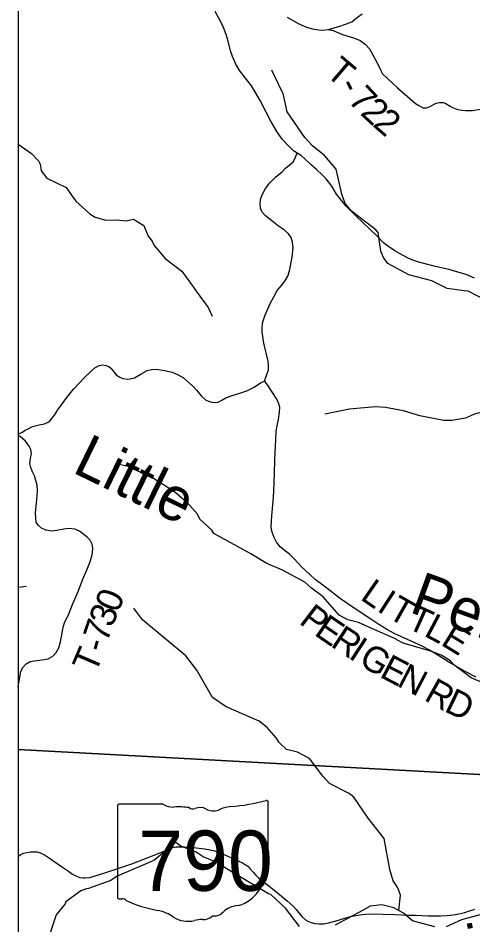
# Model space of a CAD drawing. Extents: x -1.8 to 75.7, y -2 to 25.
# Drawn here: x 43.8 to 44.794, y 18.595 to 20.577 of the extents above; entities that cross this region are included whole.
import ezdxf

# ---------------------------------------------------------------- set-up
doc = ezdxf.new("R2010")
doc.units = 0
for name, color, linetype in [('GM_X_County_Road', 7, 'Continuous'), ('GM_X_Minor_River', 7, 'Continuous'), ('GM_X_Minor_River_Text', 7, 'Continuous'), ('GM_X_State_Location', 7, 'Continuous'), ('GM_X_State_Route', 7, 'Continuous'), ('GM_X_State_Shield', 7, 'Continuous'), ('GM_X_Township', 7, 'Continuous'), ('GM_X_Township_Road', 7, 'Continuous'), ('GM_X_Township_Road_Text', 7, 'Continuous'), ('SH_Data', 7, 'Continuous')]:
    doc.layers.add(name, color=color, linetype=linetype)

msp = doc.modelspace()

# ---------------------------------------------------------------- linework, layer by layer
at = {"layer": 'GM_X_County_Road'}
for points in [[(44.7979, 20.009), (44.7792, 20.0165), (44.7663, 20.0203), (44.7442, 20.0269), (44.7092, 20.0352), (44.6757, 20.044), (44.6631, 20.0483), (44.6529, 20.0528), (44.6428, 20.0578), (44.6337, 20.063), (44.6238, 20.0689), (44.6077, 20.0795), (44.5987, 20.0863), (44.5833, 20.1023), (44.5689, 20.1159), (44.5548, 20.1291), (44.5376, 20.1456), (44.517, 20.1665), (44.5045, 20.1814), (44.4961, 20.1923), (44.4855, 20.2102), (44.4737, 20.2259), (44.4647, 20.235), (44.452, 20.2466), (44.4408, 20.2567), (44.427, 20.27), (44.4184, 20.2771), (44.41, 20.2821), (44.402, 20.2875), (44.3889, 20.3002), (44.3773, 20.3126), (44.3655, 20.3294), (44.3528, 20.3518), (44.342, 20.372), (44.3293, 20.397), (44.3192, 20.4149), (44.3102, 20.4291), (44.2972, 20.4463), (44.285, 20.462), (44.2759, 20.4768), (44.2686, 20.4936), (44.2643, 20.5059), (44.2589, 20.5268), (44.2548, 20.5416), (44.2492, 20.5571), (44.2424, 20.5709), (44.2307, 20.5918)], [(44.3885, 20.5797), (44.4121, 20.5656), (44.4304, 20.5572), (44.4433, 20.5538), (44.4571, 20.5516), (44.4655, 20.5513), (44.4777, 20.5521), (44.5012, 20.5588), (44.5178, 20.5647), (44.5293, 20.5695), (44.5389, 20.577), (44.5518, 20.5867)]]:
    msp.add_lwpolyline(points, dxfattribs=at)
at = {"layer": 'GM_X_Minor_River'}
for points in [[(44.8204, 19.9613), (44.7836, 19.9803), (44.7749, 19.981), (44.7376, 19.9863), (44.7045, 20.0026), (44.6539, 20.0163), (44.6085, 20.0409), (44.5987, 20.0542), (44.5931, 20.068), (44.5868, 20.1089), (44.5816, 20.1147), (44.5284, 20.1555), (44.5146, 20.1723), (44.5076, 20.1923), (44.4949, 20.247), (44.4694, 20.277), (44.4436, 20.2984), (44.4271, 20.316), (44.3883, 20.3723), (44.3797, 20.4128), (44.375, 20.4202), (44.3548, 20.4634)], [(43.8002, 20.302), (43.8297, 20.281), (43.8447, 20.2653), (43.8486, 20.2583), (43.8504, 20.2431), (43.8632, 20.2271), (43.9053, 20.2068), (43.9219, 20.1827), (43.9263, 20.1772), (43.9565, 20.1497), (43.9687, 20.1425), (43.9919, 20.1353), (44.0162, 20.136), (44.0361, 20.1338), (44.0525, 20.1375), (44.0752, 20.1242), (44.0846, 20.1008), (44.093, 20.0895), (44.0972, 20.0799), (44.1214, 20.0521), (44.1576, 20.0244), (44.1866, 19.9851), (44.1891, 19.9801), (44.2152, 19.9443), (44.2244, 19.9254)], [(44.824, 19.7182), (44.8004, 19.7125), (44.7978, 19.7117), (44.7777, 19.7026), (44.7483, 19.6979), (44.7309, 19.6975), (44.6783, 19.7076), (44.6424, 19.719), (44.6031, 19.7257), (44.5815, 19.7272), (44.5245, 19.7225), (44.4708, 19.7117)], [(44.8192, 19.1226), (44.7904, 19.1347), (44.7522, 19.1635), (44.7454, 19.1722), (44.7246, 19.1847), (44.7042, 19.1926), (44.6418, 19.2111), (44.6282, 19.2179), (44.6266, 19.2198), (44.5729, 19.2425), (44.5438, 19.2557), (44.5211, 19.2617), (44.5018, 19.2723), (44.4667, 19.3122), (44.4413, 19.3307), (44.4269, 19.3444), (44.3778, 19.3705), (44.3437, 19.3852), (44.3089, 19.4064), (44.2276, 19.4503), (44.2234, 19.4579), (44.197, 19.4822), (44.192, 19.4928), (44.1693, 19.5186), (44.164, 19.5228), (44.1421, 19.5417), (44.0963, 19.5705), (44.0403, 19.5974), (44.0211, 19.6015), (44.0211, 19.6011)], [(43.8002, 19.3335), (43.8078, 19.3338), (43.818, 19.3353), (43.8172, 19.3349)], [(44.6322, 18.6266), (44.6356, 18.6598), (44.6301, 18.6759), (44.6196, 18.6915), (44.6128, 18.716), (44.6005, 18.7836), (44.5655, 18.828), (44.534, 18.8738), (44.5237, 18.8821), (44.4805, 18.904), (44.4659, 18.92), (44.4372, 18.9589), (44.4111, 18.9723), (44.3864, 18.9784), (44.3702, 18.9941), (44.3652, 19.003), (44.3443, 19.0261), (44.3266, 19.0399), (44.255, 19.0714), (44.2246, 19.0918), (44.1905, 19.1517), (44.1669, 19.1829), (44.0718, 19.2615), (44.0565, 19.2821), (44.0533, 19.2871)], [(44.4148, 18.5913), (44.3845, 18.6312), (44.3528, 18.6615), (44.3471, 18.6626), (44.2661, 18.7118), (44.2313, 18.733), (44.2045, 18.7436), (44.189, 18.7535), (44.1557, 18.7671), (44.1425, 18.7761), (44.1383, 18.778), (44.1289, 18.7617), (44.1123, 18.7479), (44.0964, 18.7354), (44.0556, 18.7178), (44.0163, 18.7013), (44.0027, 18.6922), (43.9536, 18.6742), (43.9498, 18.6738), (43.9369, 18.6692), (43.9045, 18.6456), (43.9026, 18.641), (43.8833, 18.617), (43.8701, 18.5778)], [(45.1478, 18.7045), (45.1443, 18.703), (45.1182, 18.6976), (45.0933, 18.688), (45.0883, 18.6903), (45.0774, 18.6876), (45.0619, 18.6891), (45.0581, 18.6891), (45.0498, 18.691), (45.04, 18.689), (45.004, 18.6947), (44.9791, 18.6935), (44.9459, 18.6759), (44.9425, 18.6698), (44.8877, 18.6438), (44.8642, 18.6316), (44.8204, 18.6197), (44.7694, 18.6059), (44.7358, 18.5906)], [(44.7112, 18.5905), (44.6862, 18.5969), (44.662, 18.6037), (44.6427, 18.6208), (44.6212, 18.6325), (44.5951, 18.6385), (44.5694, 18.6358), (44.5528, 18.6262), (44.4927, 18.5942)]]:
    msp.add_lwpolyline(points, dxfattribs=at)
at = {"layer": 'GM_X_State_Route'}
for points in [[(43.8002, 18.7454), (43.8058, 18.7486), (43.8123, 18.7516), (43.8194, 18.7534), (43.8275, 18.7547), (43.8352, 18.7547), (43.8421, 18.7543), (43.8486, 18.7524), (43.8575, 18.7482), (43.8688, 18.7405), (43.8946, 18.7226), (43.91, 18.7121), (43.9193, 18.7056), (43.9278, 18.7012), (43.9349, 18.6987), (43.9422, 18.6979), (43.9469, 18.6977), (43.9566, 18.6987), (43.9683, 18.7018), (43.9898, 18.7087), (44.0488, 18.7287), (44.0788, 18.7399), (44.0978, 18.7476), (44.1278, 18.7599), (44.1357, 18.7632), (44.145, 18.7652), (44.1538, 18.7656), (44.1637, 18.7656), (44.1829, 18.7638), (44.2083, 18.7609), (44.2202, 18.7589), (44.2295, 18.7565), (44.252, 18.748), (44.2743, 18.7381), (44.2903, 18.7304), (44.2962, 18.7271), (44.3019, 18.7231), (44.3075, 18.7176), (44.314, 18.7099), (44.3193, 18.7042), (44.3256, 18.6979), (44.3313, 18.6927), (44.3367, 18.6886), (44.3442, 18.6829), (44.3671, 18.6649), (44.3888, 18.6467), (44.4014, 18.6357), (44.4077, 18.6288), (44.4131, 18.6223), (44.4208, 18.6124), (44.4285, 18.6057), (44.4336, 18.6027), (44.4405, 18.6003), (44.4484, 18.5982), (44.4573, 18.5974), (44.4678, 18.5974), (44.4786, 18.5992), (44.4924, 18.6031), (44.4927, 18.6032)], [(44.4927, 18.6032), (44.5163, 18.6104), (44.5304, 18.6138), (44.5465, 18.6167), (44.56, 18.6185), (44.5698, 18.6191), (44.6243, 18.6175), (44.6543, 18.6163), (44.6688, 18.6159), (44.6972, 18.6149), (44.724, 18.6148), (44.7381, 18.6157), (44.7507, 18.6171), (44.7631, 18.6191), (44.7762, 18.6223), (44.7845, 18.6248), (44.7945, 18.628), (44.798, 18.6293)]]:
    msp.add_lwpolyline(points, dxfattribs=at)
at = {"layer": 'GM_X_State_Shield'}
for p, q in [((44.017, 18.8553), (44.017, 18.6552)), ((44.1168, 18.8588), (44.0203, 18.8588)), ((44.3466, 18.7591), (44.3466, 18.8637)), ((44.3466, 18.7591), (44.3466, 18.7591))]:
    msp.add_line(p, q, dxfattribs=at)
for centre, major_axis, start_param, end_param in [((44.0208, 18.8558), (0.00382, 0), 1.712693, 3.28349), ((44.1398, 18.882), (0.037, 0), 4.042523, 4.731795), ((44.152, 18.7464), (0.133, 0), 1.404758, 1.657858), ((44.2738, 18.7977), (0.0703, 0), 1.699011, 2.107814), ((44.2292, 19.1316), (0.3495, 0), 4.814394, 5.042369), ((44.3429, 18.8642), (0.00367, 0), 6.141152, 7.989035), ((44.1822, 18.8568), (0.0107, 0), 3.836095, 5.185415), ((44.1979, 18.8337), (0.0222, 0), 0.950623, 2.079405), ((44.2266, 18.8654), (0.0267, 0), 4.081561, 5.145723), ((44.3457, 18.7514), (0.00568, 0), 1.883978, 3.671073), ((44.3427, 18.7587), (0.00393, 0), 5.05454, 6.418171), ((44.3096, 18.7381), (0.0341, 0), 5.934695, 6.695948), ((44.3597, 18.7152), (0.0248, 0), 2.387724, 3.262537), ((44.2488, 18.7019), (0.0874, 0), 5.101752, 6.440018), ((44.0208, 18.6548), (0.00385, 0), 3.00124, 4.508301), ((44.0214, 18.6753), (0.0294, 0), 4.665946, 4.897461), ((44.0274, 18.6437), (0.0106, 0), 0.519207, 1.627899), ((44.1612, 18.8235), (0.2524, 0), 4.195997, 4.488961), ((44.2856, 18.599), (0.0479, 0), 1.647645, 2.488434), ((44.086, 18.5653), (0.079, 0), 0.823519, 1.323587), ((44.2282, 18.6083), (0.00752, 0), 1.147584, 2.315152), ((44.225, 18.6358), (0.0282, 0), 4.937069, 5.64225), ((44.1714, 18.6427), (0.0501, 0), 4.026481, 4.996735), ((44.2004, 18.5735), (0.0412, 0), 1.495662, 1.94098), ((44.204, 18.6277), (0.0267, 0), 4.691044, 5.507374)]:
    msp.add_ellipse(centre, major_axis=major_axis, ratio=0.8, start_param=start_param, end_param=end_param, dxfattribs=at)
at = {"layer": 'GM_X_Township'}
for points in [[(48.1876, 22.5121), (43.8002, 22.5121), (43.8002, 18.978)], [(43.8002, 18.978), (44.8356, 18.9224), (45.3865, 18.8952), (46.1197, 18.859), (46.3714, 18.8466), (46.9192, 18.8195), (47.1815, 18.806), (47.9522, 18.7663), (48.0201, 19.5982), (48.0214, 19.6198), (48.0228, 19.6698), (48.0235, 19.6926), (48.0261, 19.7186), (48.0301, 19.7636), (48.0891, 20.7799), (48.1186, 21.2763), (48.1494, 21.7937), (48.1876, 22.5121)], [(43.8002, 18.978), (43.8002, 15.7121), (47.7632, 15.7121)], [(47.7632, 15.7121), (47.7893, 16.1371), (47.8138, 16.5363), (47.826, 16.7363), (47.8708, 17.4759), (47.8899, 17.791), (47.9266, 18.366), (47.9522, 18.7663), (47.1815, 18.806), (46.9192, 18.8195), (46.3714, 18.8466), (46.1197, 18.859), (45.3865, 18.8952), (44.8356, 18.9224), (43.8002, 18.978)]]:
    msp.add_lwpolyline(points, dxfattribs=at)
at = {"layer": 'GM_X_Township_Road'}
for points in [[(44.4777, 20.5521), (44.4886, 20.5502), (44.5094, 20.5417), (44.5353, 20.5333), (44.5476, 20.5283), (44.5589, 20.5201), (44.5681, 20.5103), (44.5763, 20.4959), (44.5856, 20.4779), (44.5926, 20.463), (44.5968, 20.4554), (44.6292, 20.4251), (44.6508, 20.4057), (44.6689, 20.3907), (44.676, 20.3862), (44.6854, 20.3815), (44.6933, 20.3813), (44.7003, 20.3839), (44.7138, 20.3912), (44.7209, 20.3931), (44.729, 20.3927), (44.7352, 20.3907), (44.7446, 20.385), (44.7495, 20.3819), (44.7604, 20.3777), (44.7702, 20.3758), (44.7779, 20.3752), (44.7929, 20.3753), (44.81, 20.3783)], [(43.8002, 19.6681), (43.8081, 19.6716), (43.8156, 19.6765), (43.8223, 19.6793), (43.8318, 19.6842), (43.8463, 19.6881), (43.8578, 19.6905), (43.869, 19.6954), (43.8797, 19.7094), (43.8868, 19.7206), (43.9064, 19.7482), (43.9208, 19.766), (43.9443, 19.7906), (43.9607, 19.8065), (43.9678, 19.8125), (43.9772, 19.8175), (43.9856, 19.819), (43.9919, 19.8181), (43.9981, 19.816), (44.0028, 19.8121), (44.0093, 19.8039), (44.0155, 19.797), (44.0222, 19.7921), (44.0291, 19.7897), (44.0381, 19.788), (44.0452, 19.7884), (44.0545, 19.7906), (44.0706, 19.8002), (44.082, 19.8067), (44.0919, 19.8091), (44.102, 19.8097), (44.1203, 19.8067), (44.1367, 19.8035), (44.15, 19.7977), (44.1614, 19.7906), (44.1823, 19.7725), (44.1903, 19.7641), (44.2008, 19.751), (44.2097, 19.7428), (44.2159, 19.7398), (44.2236, 19.7374), (44.231, 19.737), (44.2372, 19.738), (44.2456, 19.7417), (44.254, 19.7471), (44.2682, 19.7523), (44.2828, 19.7568), (44.3, 19.7626), (44.3162, 19.7703), (44.3302, 19.7796), (44.3386, 19.7835), (44.3439, 19.7979), (44.347, 19.8086), (44.3472, 19.8175), (44.3463, 19.8271), (44.3375, 19.8665), (44.3336, 19.8908), (44.3334, 19.9012), (44.3349, 19.9134), (44.3396, 19.9268), (44.3513, 19.9535), (44.3588, 19.9681), (44.3663, 19.9819), (44.3758, 19.9924), (44.3833, 20.0023), (44.3893, 20.0131), (44.3934, 20.0249), (44.3988, 20.055), (44.401, 20.0753), (44.3999, 20.0875), (44.3967, 20.0977), (44.3911, 20.106), (44.3822, 20.114), (44.3693, 20.1226), (44.3549, 20.1338), (44.3407, 20.145), (44.3338, 20.1534), (44.3297, 20.162), (44.3289, 20.1738), (44.3306, 20.1837), (44.3349, 20.1941), (44.3405, 20.2048), (44.3504, 20.2175), (44.3635, 20.2307), (44.3773, 20.2416), (44.3846, 20.2492), (44.3964, 20.2586), (44.402, 20.2636), (44.4059, 20.272), (44.41, 20.2821)], [(44.8012, 19.1368), (44.7783, 19.1482), (44.7414, 19.1693), (44.7136, 19.1869), (44.6976, 19.1962), (44.6834, 19.2041), (44.6674, 19.2116), (44.6435, 19.2223), (44.6232, 19.2315), (44.6072, 19.2402), (44.5884, 19.2519), (44.5708, 19.2629), (44.5349, 19.2876), (44.5049, 19.3075), (44.4747, 19.331), (44.4601, 19.3417), (44.4502, 19.3494), (44.4366, 19.3622), (44.421, 19.3763), (44.4034, 19.3954), (44.3929, 19.4053), (44.3873, 19.4096), (44.3736, 19.4207), (44.3651, 19.4315), (44.36, 19.4418), (44.3552, 19.4533), (44.3535, 19.4645), (44.3546, 19.4892), (44.3582, 19.5289), (44.3596, 19.5603), (44.3614, 19.6086), (44.3616, 19.6276), (44.3633, 19.655), (44.3644, 19.6741), (44.3661, 19.686), (44.3689, 19.6997), (44.3715, 19.7155), (44.3719, 19.7264), (44.3702, 19.734), (44.3657, 19.7439), (44.3435, 19.7776), (44.3386, 19.7835)], [(43.8002, 19.1151), (43.8036, 19.1363), (43.8057, 19.1487), (43.8095, 19.1572), (43.818, 19.1655), (43.8261, 19.1704), (43.8355, 19.1724), (43.8529, 19.174), (43.8656, 19.1767), (43.8758, 19.1827), (43.8832, 19.1906), (43.889, 19.2006), (43.8931, 19.2136), (43.8955, 19.2287), (43.8987, 19.2461), (43.9025, 19.2576), (43.9103, 19.273), (43.9188, 19.2952), (43.9312, 19.3241), (43.9419, 19.3504), (43.9509, 19.3723), (43.9565, 19.3869), (43.961, 19.401), (43.963, 19.4091), (43.9637, 19.418), (43.9623, 19.4272), (43.9578, 19.4357), (43.9513, 19.4425), (43.9341, 19.4555), (43.9244, 19.4602), (43.9105, 19.4618), (43.8998, 19.4602), (43.885, 19.4573), (43.8733, 19.4559), (43.8606, 19.4577), (43.8512, 19.462), (43.8444, 19.4682), (43.8399, 19.4756), (43.8386, 19.4839), (43.8384, 19.4965), (43.8402, 19.5169), (43.8424, 19.5433), (43.8415, 19.5563), (43.8391, 19.5662), (43.8359, 19.5767), (43.831, 19.5866), (43.8276, 19.5951), (43.8258, 19.6036), (43.8272, 19.6146), (43.8292, 19.6253), (43.8278, 19.6341), (43.8245, 19.6415), (43.816, 19.6522), (43.8048, 19.6628), (43.8002, 19.6652)]]:
    msp.add_lwpolyline(points, dxfattribs=at)
at = {"layer": 'SH_Data'}
msp.add_line((43.8002, 22.5121), (43.8002, 15.7121), dxfattribs=at)
msp.add_line((43.8002, 22.5121), (43.8002, 15.7121), dxfattribs=at)

# ---------------------------------------------------------------- texts
at = {"layer": 'GM_X_Minor_River_Text'}
for s, height, rotation, p in [('Little', 0.0947, 333.998, (43.9159, 19.5855)), ('Perigen', 0.09469, 340.0029, (44.6524, 19.2796)), ('Perigen', 0.0947, 10.0083, (44.5959, 18.4636))]:
    msp.add_text(s, height=height, rotation=rotation, dxfattribs=at).set_placement(p)
at = {"layer": 'GM_X_State_Location'}
for s in ['s', 'r']:
    msp.add_text(s, height=0.000189, dxfattribs=at).set_placement((44.1781, 18.742))
msp.add_text('790', height=0.000189, rotation=0, dxfattribs=at).set_placement((44.1112, 18.7282))
at = {"layer": 'GM_X_State_Shield'}
msp.add_text('790', height=0.13184, dxfattribs=at).set_placement((44.0626, 18.6693))
at = {"layer": 'GM_X_Township_Road_Text'}
for s, rotation, p in [('T', 319.5365, (44.4698, 20.4541)), ('-', 297.4099, (44.4986, 20.431)), ('7', 313.1101, (44.5191, 20.3965)), ('2', 317.0527, (44.546, 20.368)), ('2', 318.7527, (44.573, 20.3429)), ('L', 325.4107, (44.5457, 19.3079)), ('0', 67.5356, (44.0183, 19.2752)), ('I', 327.159, (44.5823, 19.2827)), ('T', 330.5158, (44.6049, 19.2682)), ('3', 68.5958, (44.0056, 19.2429)), ('P', 322.463, (44.4119, 19.2553)), ('T', 335.7988, (44.6469, 19.2448)), ('E', 325.5485, (44.445, 19.23)), ('L', 332.1047, (44.6848, 19.2278)), ('7', 71.2343, (43.9946, 19.2104)), ('R', 326.635, (44.481, 19.2053)), ('E', 328.4839, (44.7216, 19.2084)), ('-', 73.8409, (43.9883, 19.1886)), ('I', 326.7269, (44.5201, 19.1796)), ('T', 66.7015, (43.9689, 19.1423)), ('G', 329.3578, (44.542, 19.1653)), ('E', 332.4783, (44.588, 19.1381)), ('N', 332.4428, (44.6257, 19.1185)), ('R', 330.8612, (44.6851, 19.0874)), ('D', 334.4086, (44.7292, 19.0629))]:
    msp.add_text(s, height=0.0568, rotation=rotation, dxfattribs=at).set_placement(p)

doc.saveas('drawing.dxf')
